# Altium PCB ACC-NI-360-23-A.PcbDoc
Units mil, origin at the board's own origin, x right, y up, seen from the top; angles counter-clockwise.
Board outline 2000 x 2500 mil, 2 copper layers (Top Layer, Bottom Layer), stack 22.756 mil thick; 31 components, 12 nets, 67 pads, 613 vias.
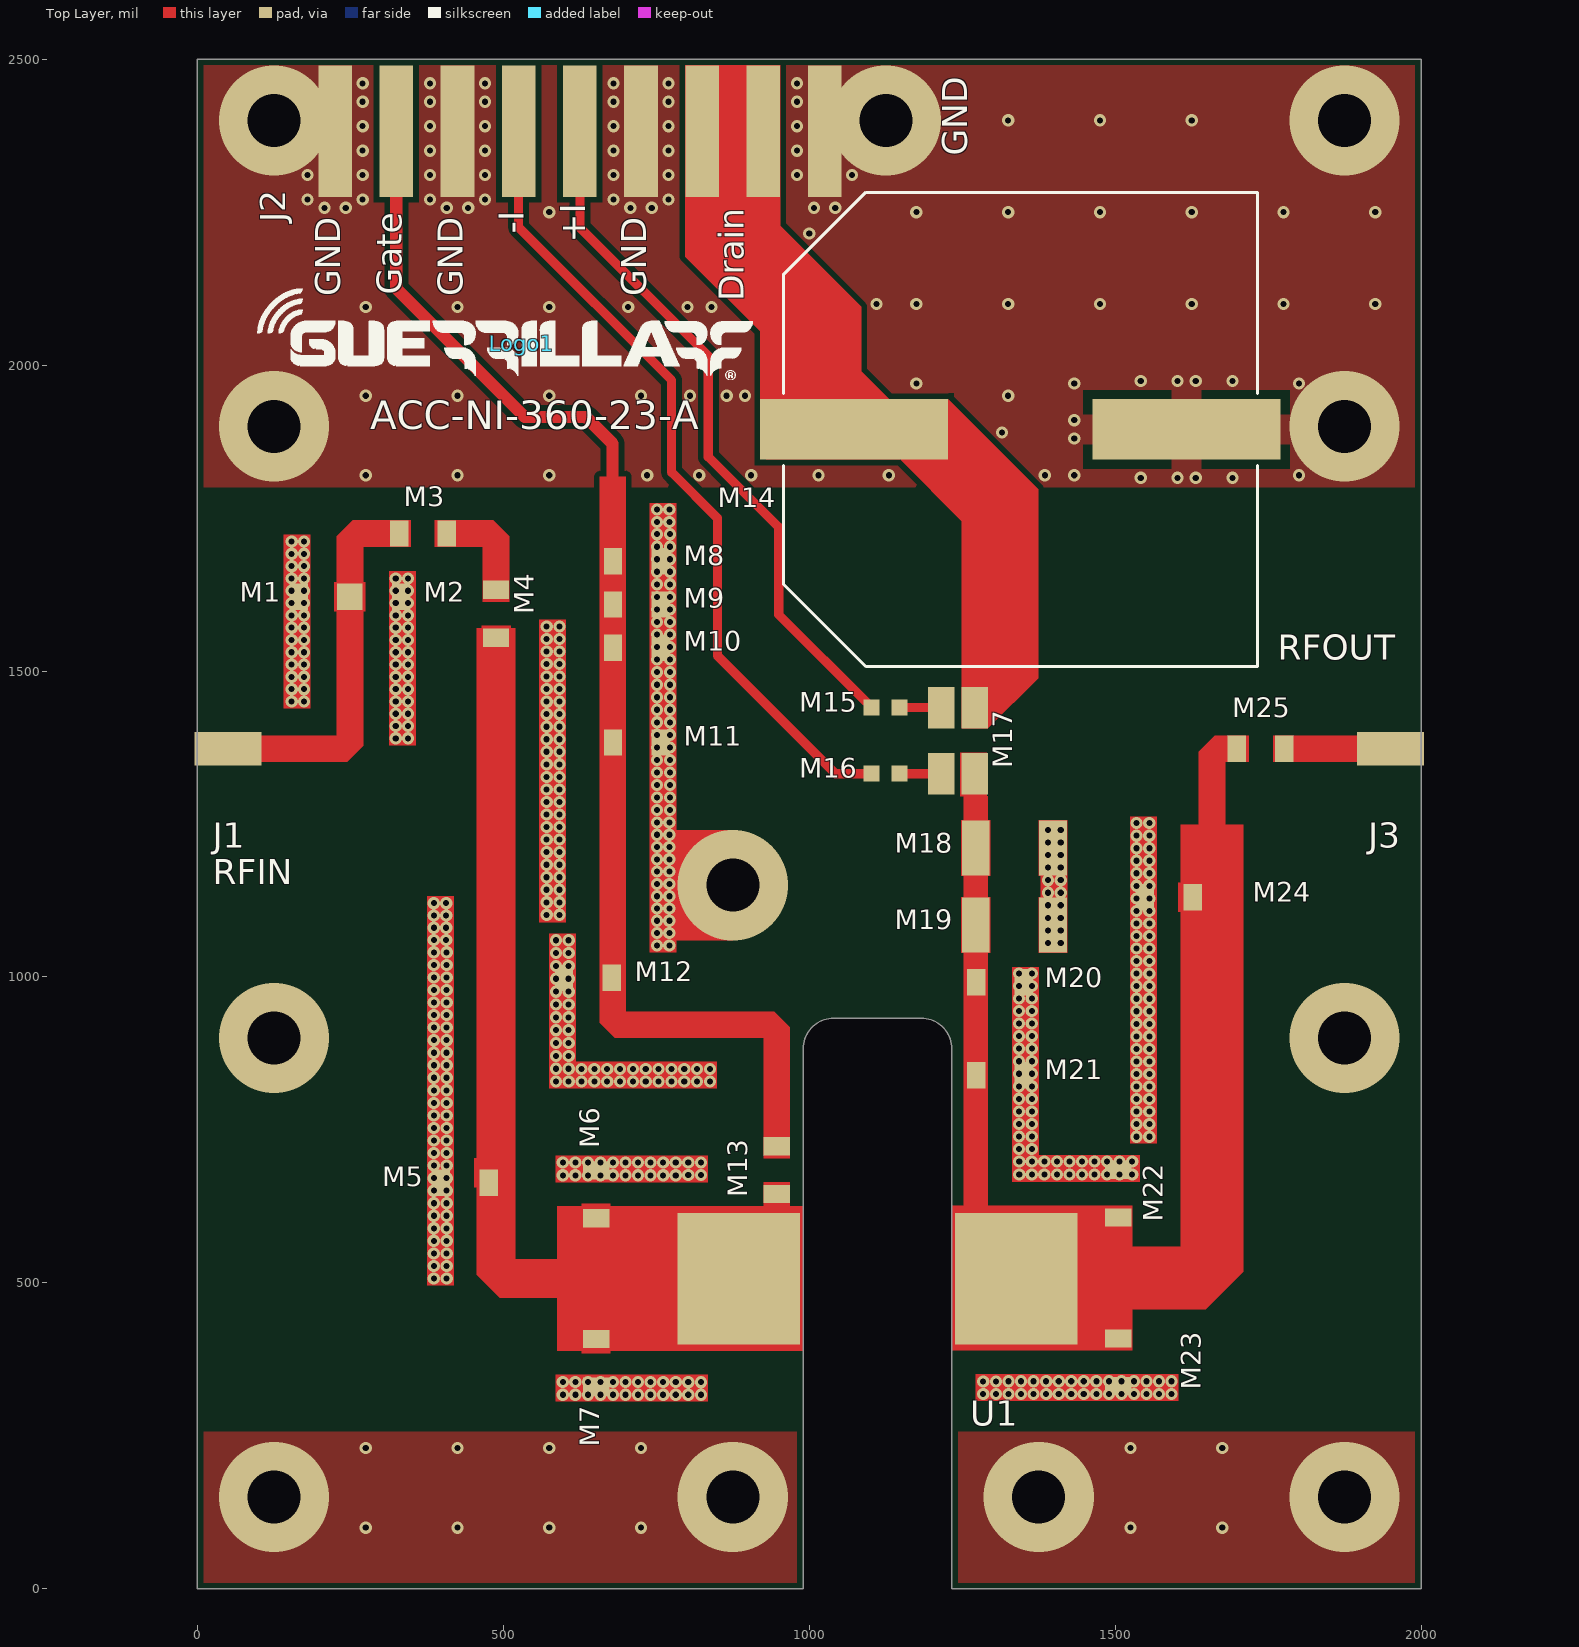
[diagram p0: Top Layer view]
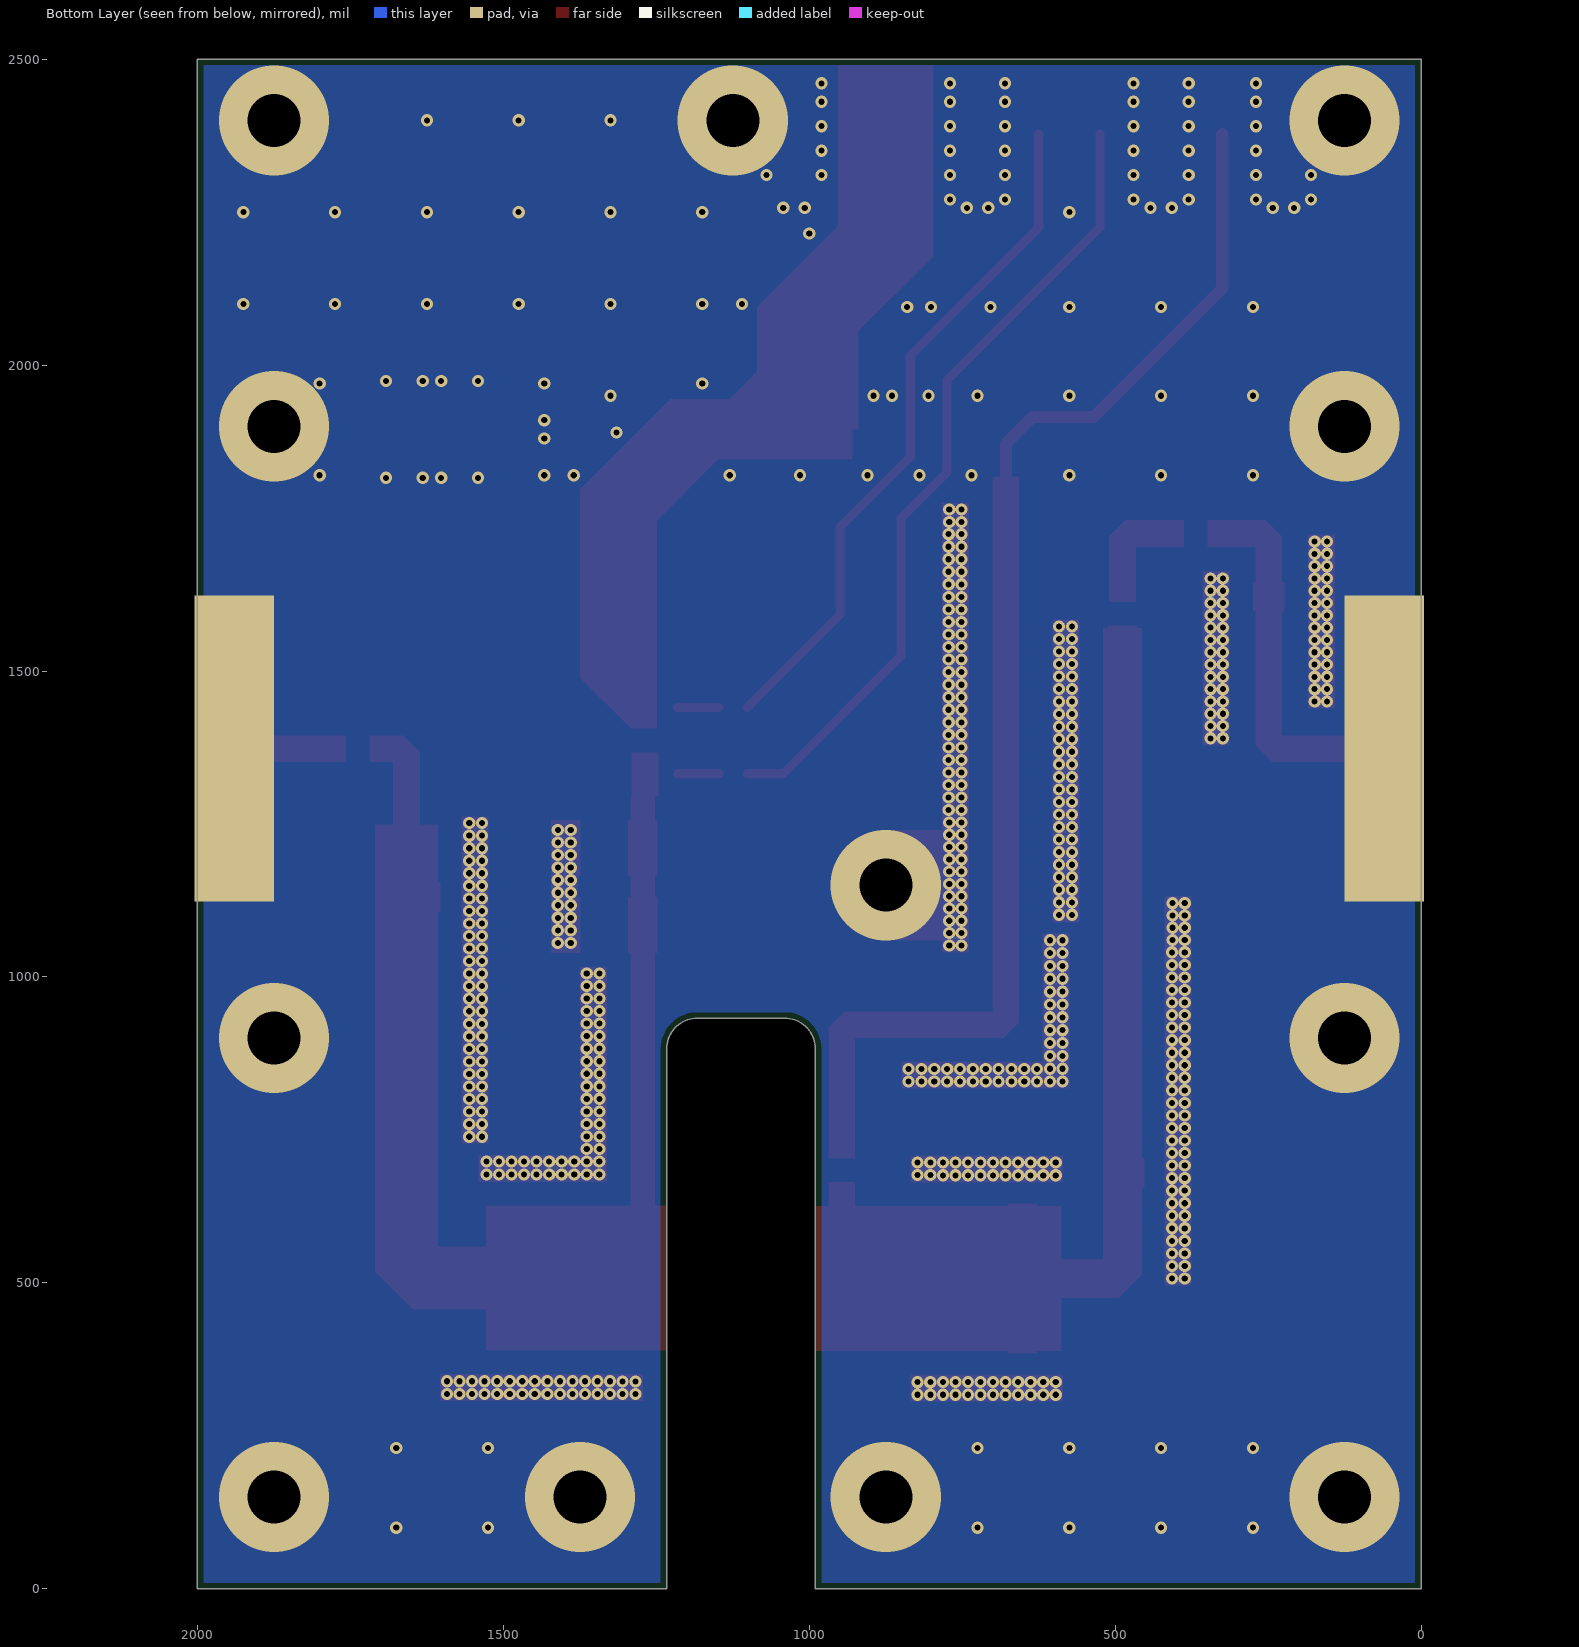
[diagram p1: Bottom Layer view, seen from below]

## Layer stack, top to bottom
Top Layer: signal copper 1.378
Dielectric 1: prepreg 20, RO4350B, Dk 3.48
Bottom Layer: signal copper 1.378

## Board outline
0,0 0,2500 2000,2500 2000,0 1233,0 1233,882.5 ccw(c1183,882.5) 1183,932.5 1040,932.5 ccw(c1040,882.5) 990,882.5 990,0

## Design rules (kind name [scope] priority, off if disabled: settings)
BackDrilling [IsVia and not InNet('GND')] p1: maxstublength=5 usetopbackdrill=TRUE usebottombackdrill=TRUE holeoversize=10 holetolplus=0.2 holetolminus=0.2
BoardOutlineClearance BoardOutlineClearance_Solder_Mask [OnLayer('Top Solder') Or OnLayer('Bottom Solder')] p1: gap=0 ignorepadtopadclearanceinfootprint=FALSE
BoardOutlineClearance [All] p2: gap=10 ignorepadtopadclearanceinfootprint=FALSE
Clearance Clearance_I/O [InNetClass('I/O') vs InNet('GND')] p1: gap=7 ignorepadtopadclearanceinfootprint=TRUE
Clearance Clearance_RF_Strip [InNetClass('RF_Strip') vs InNet('GND')] p2: gap=40 ignorepadtopadclearanceinfootprint=TRUE
Clearance Clearance_RF_15-15-8 [InNetClass('RF_15-15-8') vs InNet('GND')] p3: gap=15 ignorepadtopadclearanceinfootprint=TRUE
Clearance Clearance_RF_20-10-12 [InNetClass('RF_20-10-12') vs InNet('GND')] p4: gap=10 ignorepadtopadclearanceinfootprint=TRUE
Clearance Clearance_RF_30-20-16 [InNetClass('RF_30-20-16') vs InNet('GND')] p5: gap=20 ignorepadtopadclearanceinfootprint=TRUE
Clearance Clearance_RF_28-21-16_FR4 [InNetClass('RF_28-21-16_FR4') vs InNet('GND')] p6: gap=21 ignorepadtopadclearanceinfootprint=TRUE
Clearance Clearance_RF_15-27p5-8 [InNetClass('RF_15-27p5-8') vs InNet('GND')] p7: gap=27.5 ignorepadtopadclearanceinfootprint=TRUE
Clearance Clearance_RF_25-22-40_75ohm [InNetClass('RF_25-22-40_75ohm') vs InNet('GND')] p8: gap=22 ignorepadtopadclearanceinfootprint=TRUE
Clearance Clearance_GND [InNet('GND')] p9: gap=10 ignorepadtopadclearanceinfootprint=TRUE
Clearance [All] p10: gap=6 ignorepadtopadclearanceinfootprint=TRUE
ComponentClearance ComponentClearance_Heatsink [InComponent('All') And OnLayer('Top Layer') vs HasFootprint('Heatsink_wFid')] p1: gap=0 collisioncheckmode=3 verticalgap=0 showdistances=FALSE
ComponentClearance ComponentClearance_PCB_Frame [InComponent('All') And OnLayer('Top Layer') vs HasFootprint('PCB_Frame')] p2: gap=0 collisioncheckmode=3 verticalgap=0 showdistances=FALSE
ComponentClearance [All] p3: gap=10 collisioncheckmode=3 verticalgap=10 showdistances=TRUE
HoleSize [All] p1: absolutevalues=TRUE maxlimit=200 minlimit=8 maxpercent=80.000 minpercent=20.000
MinimumSolderMaskSliver [All] p1: minsoldermaskwidth=5
PlaneClearance [Not InNet('GND')] p1: clearance=20
PlaneConnect [InNet('GND')] p1: planeconnectstyle=Direct reliefexpansion=20 reliefentries=4 reliefconductorwidth=10 reliefairgap=10
PolygonConnect [All vs InNet('GND')] p1: connectstyle=Direct reliefconductorwidth=10 reliefentries=4 polygonreliefangle="90 Angle" airgapwidth=10
RoutingVias [All] p1: holewidth=10 width=20 viastyle="Through Hole" minholewidth=8 minwidth=18 maxholewidth=23.62 maxwidth=33.62
SilkToSilkClearance [All] p1: silktosilkclearance=5
SilkToSolderMaskClearance [IsPad] p1: minsilkscreentomaskgap=5 clearancetoexposedcopper=TRUE
SolderMaskExpansion [All] p1: expansion=1 istentingtop=FALSE
UnRoutedNet [All] p1: checkbadconnections=TRUE
Width [All] p1: maxlimit=100 minlimit=6 preferedwidth=10
22 further rules are at their usual default settings.

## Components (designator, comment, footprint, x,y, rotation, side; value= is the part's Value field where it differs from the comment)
F66 "Comment" PCB_Fab_30T-20G-16D_4003 166.62,-1553 r0 top locked
J1 "SMA Panel Mount_RevB" "SMA Panel Mount_RevB" 0,1373.14 r0 top locked
J2 "Header_H_9-Pin_100mil" Header_H_9-Pin_100mil 625,2500 r0 top
J3 "SMA Panel Mount_RevB" "SMA Panel Mount_RevB" 2000,1373.14 r180 top locked
Logo1 "GRF_2021_Full" GRF_2021_Full 530,2035 r0 top
M1 "0805_30x70x42" 0805_30x70x42 204.41,1621.17 r0 top
M2 "0805_30x70x42" 0805_30x70x42 293.78,1621.17 r180 top
M3 "0805_30x70x42" 0805_30x70x42 368.59,1724.91 r180 top
M4 "0805_30x70x42" 0805_30x70x42 488.07,1593.61 r90 top
M5 "0805_30x70x42" 0805_30x70x42 436.89,663.5 r0 top
M6 "0805_30x70x42" 0805_30x70x42 651.85,644.8 r270 top (schematic designator M7)
M7 "0805_30x70x42" 0805_30x70x42 651.85,369.21 r90 top (schematic designator M6)
M8 "0805_30x70x42" 0805_30x70x42 718.31,1679.56 r180 top
M9 "0805_30x70x42" 0805_30x70x42 718.31,1608.69 r180 top
M10 "0805_30x70x42" 0805_30x70x42 718.31,1537.82 r180 top
M11 "0805_30x70x42" 0805_30x70x42 718.31,1383.3 r180 top
M12 "0805_30x70x42" 0805_30x70x42 638.19,998.89 r0 top
M13 "0805_30x70x42" 0805_30x70x42 946.74,684.17 r90 top
M14 "Comment" Panasonic_K-Size 1345,1895 r0 top
M15 "0402_26x26x20" 0402_26x26x20 1124.41,1440.25 r180 top
M16 "0402_26x26x20" 0402_26x26x20 1124.41,1332.25 r180 top
M17 "Ohmite_LVK12" Ohmite_LVK12 1243.01,1386.25 r270 top
M18 "1210_45x120x75" 1210_45x120x75 1335.32,1211.08 r0 top
M19 "1210_45x120x75" 1210_45x120x75 1335.32,1084.76 r0 top
M20 "0805_30x70x42" 0805_30x70x42 1311.7,991.25 r180 top
M21 "0805_30x70x42" 0805_30x70x42 1311.7,839.22 r180 top
M22 "0805_30x70x42" 0805_30x70x42 1505,645.78 r270 top
M23 "0805_30x70x42" 0805_30x70x42 1505,370.19 r90 top
M24 "0805_30x70x42" 0805_30x70x42 1587.57,1130.03 r0 top
M25 "0805_30x70x42" 0805_30x70x42 1737.48,1373.14 r180 top
U1 "ACC-NI-360_RevA" ACC-NI-360_RevA 1111.5,507 r0 top locked

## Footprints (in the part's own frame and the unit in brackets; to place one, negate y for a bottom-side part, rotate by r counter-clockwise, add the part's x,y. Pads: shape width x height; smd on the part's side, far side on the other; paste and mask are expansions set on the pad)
0402_26x26x20 [mil] "0402 RL (RF Choke)"
  rect 26x26 smd: 1(-23,0) 2(23,0)
0805_30x70x42 [mil] "Generic 0805 SMD"
  rect 30x43 smd: 1(-39,0) 2(39,0)
1210_45x120x75 [mil] "Generic 1210 SMD"
  rect 45x90 smd: 1(-63,0) 2(63,0)
ACC-NI-360_RevA [mil] "Standard Footprint"
  rect 200.5x215 smd paste-3937.01: 1(226.75,0) 2(-226.75,0)
GRF_2021_Full [mil] "2021 Guerrilla RF Logo"
  silkscreen extent -432,-59 378,90
Header_H_9-Pin_100mil [mil] "Generic Flat Header"
  rect 55x215 smd paste-28: 1(-400,-117.5) 2(-300,-117.5) 3(-200,-117.5) 4(-100,-117.5) 5(0,-117.5) 6(100,-117.5) 7(200,-117.5) 8(300,-117.5) 9(400,-117.5)
Ohmite_LVK12 [mil] "Current Sense Resistor"
  rect 68x43 smd: 1(-54,-27.5) 2(54,-27.5) 3(54,27.5) 4(-54,27.5)
Panasonic_K-Size [mil] "EEV-FK2A221M Capacitor"
  rect 307x98.5 smd: 1(271.65,0) 2(-271.65,0)
  silkscreen extent -387,-387 387,387
PCB_Fab_30T-20G-16D_4003 [mil] "STD RF&Stack  30mil RF 20mil Gap  16mil Dielectric"
"SMA Panel Mount_RevB" [mil] "901-2GB100000AE"
  rect 110x55 smd paste-50: 1(50,0)
  rect 130x500 smd far side paste-50: 2(60,0)

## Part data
J1 J3: library part RF_Conn
J2: library part Header_9-Pin, "Header 9-Pin"
Logo1: library part GRF_Logo, "=CurrentFootprint"
M1 M2 M3 M4 M5 M6 M7 M8 M9 M10 M11 M12 M14 M18 M19 M20 M21 M22 M23 M24 M25: library part Capacitor
M13 M15 M16: library part Resistor
M17: library part Resistor_Ohmite_Current_Sense
U1: library part ACC-NI-360, "ACC-NI-360"

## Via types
v1: diameter 20/20 (per signal layer), hole 10, Top Layer to Bottom Layer, tented top, 486 vias
v2: diameter 20/20 (per signal layer), hole 10, Top Layer to Bottom Layer, 115 vias
v3: diameter 180/180 (per signal layer), hole 86.61, Top Layer to Bottom Layer, 12 vias

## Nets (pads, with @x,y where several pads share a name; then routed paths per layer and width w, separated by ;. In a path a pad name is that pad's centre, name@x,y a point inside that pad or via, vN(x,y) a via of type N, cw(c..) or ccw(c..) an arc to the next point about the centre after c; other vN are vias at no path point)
GND: J1.2 J2.1 J2.3 J2.6 J2.9 J3.2 M1.1 M2.1 M5.1 M6.1 M7.1 M8.1 M9.1 M10.1 M11.1 M12.1 M14.1 M18.2 M19.2 M20.1 M21.1 M22.1 M23.1 M24.1
  other v1: 597.16,317.21 617.66,317.21 638.16,317.21 658.66,317.21 679.16,317.21 699.66,317.21 720.16,317.21 740.66,317.21 761.16,317.21 781.66,317.21 802.16,317.21 823.16,317.21 1284.14,318.19 1305.14,318.19 1325.64,318.19 1346.14,318.19 1366.64,318.19 1387.14,318.19 1407.64,318.19 1428.14,318.19 1448.64,318.19 1469.14,318.19 1489.64,318.19 1510.14,318.19 1530.64,318.19 1551.14,318.19 1571.64,318.19 1592.14,318.19 597.16,338.21 617.66,338.21 638.16,338.21 658.66,338.21 679.16,338.21 699.66,338.21 720.16,338.21 740.66,338.21 761.16,338.21 781.66,338.21 802.16,337.71 823.16,337.71 1284.14,338.69 1305.14,338.69 1325.64,339.19 1346.14,339.19 1366.64,339.19 1387.14,339.19 1407.64,339.19 1428.14,339.19 1448.64,339.19 1469.14,339.19 1489.64,339.19 1510.14,339.19 1530.64,339.19 1551.14,339.19 1571.64,339.19 1592.14,339.19 386.37,507.2 407.37,507.2 386.37,527.7 407.37,527.7 386.37,548.2 407.37,548.2 386.37,568.7 407.37,568.7 386.37,589.2 407.37,589.2 386.37,609.7 407.37,609.7 386.37,630.2 407.37,630.2 386.37,650.7 407.37,650.7 386.37,671.2 407.37,671.2 597.16,675.79 617.66,675.79 638.16,675.79 658.66,675.79 679.16,675.79 699.66,675.79 720.16,675.79 740.66,675.79 761.16,675.79 781.66,675.79 802.16,676.29 823.16,676.29 1343.19,677.28 1363.69,677.28 1384.19,677.28 1404.69,677.28 1425.19,677.28 1445.69,677.28 1466.19,677.28 1486.69,677.28 1507.19,677.28 1527.69,677.28 386.37,691.7 407.37,691.7 597.16,696.79 617.66,696.79 638.16,696.79 658.66,696.79 679.16,696.79 699.66,696.79 720.16,696.79 740.66,696.79 761.16,696.79 781.66,696.79 802.16,696.79 823.16,696.79 1343.19,698.28 1363.69,698.28 1384.19,698.28 1404.69,698.28 1425.19,698.28 1445.69,698.28 1466.19,698.28 1486.69,698.28 1507.19,698.28 1527.69,698.28 386.37,712.2 407.37,712.2 1342.69,718.78 1363.69,718.78 386.37,732.7 407.37,732.7 1342.69,739.28 1363.69,739.28 1534.79,738.93 1555.79,738.93 386.37,753.2 407.37,753.2 1534.79,759.43 1555.79,759.43 1342.69,759.78 1363.69,759.78 386.37,773.7 407.37,773.7 1342.69,780.28 1363.69,780.28 1534.79,779.93 1555.79,779.93 386.37,794.2 407.37,794.2 1534.79,800.43 1555.79,800.43 1342.69,800.78 1363.69,800.78 386.37,814.7 407.37,814.7 1342.69,821.28 1363.69,821.28 1534.79,820.93 1555.79,820.93 586.19,829.02 606.69,829.02 627.69,829.02 648.69,829.02 669.69,829.02 690.69,829.02 711.69,829.02 732.69,829.02 753.69,829.02 774.69,829.02 795.69,829.02 816.69,829.02 837.69,829.02 386.37,835.2 407.37,835.2 1534.79,841.43 1555.79,841.43 1342.69,841.78 1363.69,841.78 586.19,850.02 606.69,850.02 627.69,849.52 648.69,849.52 669.69,849.52 690.69,849.52 711.69,849.52 732.69,849.52 753.69,849.52 774.69,849.52 795.69,849.52 816.69,849.52 837.69,849.52 386.37,855.7 407.37,855.7 1342.69,862.28 1363.69,862.28 1534.79,861.93 1555.79,861.93 586.19,871.02 606.69,871.02 386.37,876.2 407.37,876.2 1534.79,882.43 1555.79,882.43 1342.69,882.78 1363.69,882.78 586.19,892.02 606.69,892.02 386.37,896.7 407.37,896.7 1342.69,903.28 1363.69,903.28 1534.79,902.93 1555.79,902.93 586.19,913.02 606.69,913.02 386.37,917.2 407.37,917.2 1534.79,923.43 1555.79,923.43 1342.69,923.78 1363.69,923.78 586.19,934.02 606.69,934.02 386.37,937.7 407.37,937.7 1342.69,944.28 1363.69,944.28 1534.79,943.93 1555.79,943.93 586.19,955.02 606.69,955.02 386.37,958.2 407.37,958.2 1534.79,964.43 1555.79,964.43 1342.69,964.78 1363.69,964.78 586.19,976.02 606.69,976.02 386.37,978.7 407.37,978.7 1342.69,985.28 1363.69,985.28 1534.79,984.93 1555.79,984.93 586.19,997.02 606.69,997.02 386.37,999.2 407.37,999.2 1534.79,1005.43 1555.79,1005.43 1342.69,1005.78 1363.69,1005.78 586.19,1018.02 606.69,1018.02 386.37,1019.7 407.37,1019.7 1534.79,1025.93 1555.79,1025.93 586.19,1039.02 606.69,1039.02 386.37,1040.2 407.37,1040.2 1534.79,1046.43 1555.79,1046.43 751.18,1051.58 771.28,1051.58 1389.94,1055.67 1410.94,1055.67 386.37,1060.3 406.47,1060.3 586.19,1060.02 606.69,1060.02 1534.79,1066.93 1555.79,1066.93 751.18,1071.68 771.28,1071.68 1389.94,1076.17 1410.94,1076.17 386.37,1080.4 406.47,1080.4 1534.79,1087.43 1555.79,1087.43 751.18,1091.78 771.28,1091.78 1389.94,1096.67 1410.94,1096.67 386.37,1100.5 406.47,1100.5 570.75,1101.49 591.75,1101.49 1534.79,1107.93 1555.79,1107.93 751.18,1111.88 771.28,1111.88 1389.94,1117.17 1410.94,1117.17 386.37,1120.6 406.47,1120.6 570.75,1121.99 591.75,1121.99 1534.79,1128.43 1555.79,1128.43 751.18,1131.98 771.28,1131.98 1389.94,1137.67 1410.94,1137.67 570.75,1142.49 591.75,1142.49 1534.79,1148.93 1555.79,1148.93 751.18,1152.08 771.28,1152.08 1389.94,1158.17 1410.94,1158.17 570.75,1162.99 591.75,1162.99 1534.79,1169.43 1555.79,1169.43 751.18,1172.18 771.28,1172.18 1389.94,1178.67 1410.94,1178.67 570.75,1183.49 591.75,1183.49 1534.79,1189.93 1555.79,1189.93 751.18,1192.28 771.28,1192.28 1389.94,1199.17 1410.94,1199.17 570.75,1203.99 591.75,1203.99 1534.79,1210.43 1555.79,1210.43 751.18,1212.38 771.28,1212.38 1389.94,1219.67 1410.94,1219.67 570.75,1224.49 591.75,1224.49 1534.79,1230.93 1555.79,1230.93 751.18,1232.48 771.28,1232.48 1389.94,1240.17 1410.94,1240.17 570.75,1244.99 591.75,1244.99 1534.79,1251.43 1555.79,1251.43 751.18,1252.58 771.28,1252.58 570.75,1265.49 591.75,1265.49 751.18,1272.68 772.18,1272.68 570.75,1285.99 591.75,1285.99 751.18,1293.18 772.18,1293.18 570.75,1306.49 591.75,1306.49 751.18,1313.68 772.18,1313.68 570.75,1326.99 591.75,1326.99 751.18,1334.18 772.18,1334.18 570.75,1347.49 591.75,1347.49 751.18,1354.68 772.18,1354.68 570.75,1367.99 591.75,1367.99 751.18,1375.18 772.18,1375.18 570.75,1388.49 591.75,1388.49 324.12,1390.02 344.22,1390.02 751.18,1395.68 772.18,1395.68 570.75,1408.99 591.75,1408.99 324.12,1410.12 344.22,1410.12 751.18,1416.18 772.18,1416.18 570.75,1429.49 591.75,1429.49 324.12,1430.22 344.22,1430.22 751.18,1436.68 772.18,1436.68 153.97,1450.32 174.07,1450.32 324.12,1450.32 344.22,1450.32 570.75,1449.99 591.75,1449.99 751.18,1457.18 772.18,1457.18 153.97,1470.42 174.07,1470.42 324.12,1470.42 344.22,1470.42 570.75,1470.49 591.75,1470.49 751.18,1477.68 772.18,1477.68 153.97,1490.52 174.07,1490.52 324.12,1490.52 344.22,1490.52 570.75,1490.99 591.75,1490.99 751.18,1498.18 772.18,1498.18 153.97,1510.62 174.07,1510.62 324.12,1510.62 344.22,1510.62 570.75,1511.49 591.75,1511.49 751.18,1518.68 772.18,1518.68 153.97,1530.72 174.07,1530.72 324.12,1530.72 344.22,1530.72 570.75,1531.99 591.75,1531.99 751.18,1539.18 772.18,1539.18 153.97,1550.82 174.07,1550.82 324.12,1550.82 344.22,1550.82 570.75,1552.49 591.75,1552.49 751.18,1559.68 772.18,1559.68 153.97,1570.92 174.07,1570.92 324.12,1570.92 344.22,1570.92 570.75,1572.99 591.75,1572.99 751.18,1580.18 772.18,1580.18 153.97,1591.02 174.07,1591.02 324.12,1591.02 344.22,1591.02 751.18,1600.68 772.18,1600.68 153.97,1611.12 174.07,1611.12 324.12,1611.12 344.22,1611.12 751.18,1621.18 772.18,1621.18 153.97,1631.22 174.07,1631.22 324.12,1631.22 344.22,1631.22 751.18,1641.68 772.18,1641.68 153.97,1651.32 174.07,1651.32 324.12,1651.32 344.22,1651.32 751.18,1662.18 772.18,1662.18 153.97,1671.42 174.07,1671.42 751.18,1682.68 772.18,1682.68 153.97,1691.52 174.07,1691.52 751.18,1703.18 772.18,1703.18 153.97,1711.62 174.07,1711.62 751.18,1723.68 772.18,1723.68 751.18,1743.78 771.28,1743.78 751.18,1763.88 771.28,1763.88
  other v2: 275,100 425,100 575,100 725,100 1525,100 1675,100 275,230 425,230 575,230 725,230 1525,230 1675,230 1541.65,1815.79 1601.65,1815.79 1631.65,1815.79 1691.65,1815.79 275,1820 425,1820 575,1820 735,1820 820,1820 905,1820 1015,1820 1130,1820 1385,1820 1433.11,1820 1800.2,1820 1433.11,1880 1315,1890 1433.11,1910 275,1950 425,1950 575,1950 725,1950 805,1950 865,1950 895,1950 1325,1950 1175,1970 1433.11,1970 1800.2,1970 1541.65,1974.21 1601.65,1974.21 1631.65,1974.21 1691.65,1974.21 275,2095 425,2095 575,2095 704,2095 801,2095 840,2095 1110,2100 1175,2100 1325,2100 1475,2100 1625,2100 1775,2100 1925,2100 1000,2215 575,2250 1175,2250 1325,2250 1475,2250 1625,2250 1775,2250 1925,2250 207.5,2257 242.5,2257 407.5,2257 442.5,2257 707.5,2257 742.5,2257 1007.5,2257 1042.5,2257 180,2270.5 270,2270.5 380,2270.5 470,2270.5 680,2270.5 770,2270.5 180,2310.5 270,2310.5 380,2310.5 470,2310.5 680,2310.5 770,2310.5 980,2310.5 1070,2310.5 270,2350.5 380,2350.5 470,2350.5 680,2350.5 770,2350.5 980,2350.5 270,2390.5 380,2390.5 470,2390.5 680,2390.5 770,2390.5 980,2390.5 1325,2400 1475,2400 1625,2400 270,2430.5 380,2430.5 470,2430.5 680,2430.5 770,2430.5 980,2430.5 270,2460.5 380,2460.5 470,2460.5 680,2460.5 770,2460.5 980,2460.5
  other v3: 125,150 875,150 1375,150 1875,150 125,900 1875,900 875,1150 125,1900 1875,1900 125,2400 1125,2400 1875,2400
NetJ1_1: J1.1 M1.2 M2.2 M3.2
NetJ2_2: J2.2 M8.2 M9.2 M10.2 M11.2 M12.2 M13.2 | length 765.1
  Top Layer w20: J2.2@325,2377.5 325,2125 535,1915 635,1915 678.35,1871.65 678.35,1817.35
NetJ2_4: J2.4 M16.2 | length 1318.4
  Top Layer w15: J2.4@525,2377.5 525,2225 775,1975 775,1825 850,1750 850,1525 1042.75,1332.25 M16.2
NetJ2_5: J2.5 M15.2 | length 1135.2
  Top Layer w15: J2.5@625,2377.5 625,2225 835,2015 835,1850 950,1735 950,1592.25 1095.91,1446.34 1095.91,1445.75 M15.2 M15.2@1102,1440.25
NetJ2_7: J2.7 J2.8 M14.2 M17.4
NetJ3_1: J3.1 M25.1
NetM3_1: M3.1 M4.2
NetM4_1: M4.1 M5.2 M6.2 M7.2 M13.1 U1.2
NetM15_1: M15.1 M17.1 | length 68.1
  Top Layer w15: M15.1 M17.1
NetM16_1: M16.1 M17.2 | length 68.1
  Top Layer w15: M16.1 M17.2
NetM17_3: M17.3 M18.1 M19.1 M20.2 M21.2 M22.2 M23.2 M24.2 M25.2 U1.1

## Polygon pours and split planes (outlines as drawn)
GND on Top Layer "NONET_L-01_P-001" (solid, pour order 18): 0,2500 0,1800 2000,1800 2000,2500
GND on Top Layer "NONET_L-01_P-001" (solid, pour order 16): 0,0 0,257 2000,257 2000,0
GND on Bottom Layer "NONET_L-01_P-001" (solid, pour order 17): 0,2500 0,0 2000,0 2000,2500
no net on Top Solder "NONET_L-01_P-001" (solid): 0,1775 2000,1775 2000,282 0,282

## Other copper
Top Layer:
  region net GND: 875,1240 770.69,1240 770.69,1060 875,1060
  region net GND: 575.2,818.02 849,818.02 849,861.33 618.5,861.33 618.5,1071 575.2,1071
  region net GND: 184.73,1439 141.42,1439 141.42,1723 184.73,1723
  region net NetJ2_7: 1292.01,1406.25 1249.01,1406.25 1249.01,1745.2 1148.46,1845.75 929.85,1845.75 929.85,1944.25 1226.85,1944.25 1374.01,1797.09 1374.01,1488.25
  region net NetJ2_7: 797.5,2490 797.5,2177.5 919.85,2055.15 919.85,1895 1226.85,1895 1226.85,1944.25 1130.75,1944.25 1084.85,1990.15 1084.85,2095.15 952.5,2227.5 952.5,2490
  region net GND: 739.37,1774 739.37,1040 782.68,1040 782.68,1774
  region net NetJ2_2: 925.67,703.85 967.8,703.85 967.8,917.55 942.52,942.83 700,942.83 700,1762.23 700,1817.35 657.87,1817.35 657.87,1762.23 657.87,925.28 682.45,900.7 925.67,900.7
  region net GND: 586,707.79 586,664.48 834,664.48 834,707.79
  region net NetM4_1: 588.47,625.11 627.84,625.11 627.84,629.05 675.08,629.05 675.08,625.11 925.67,625.11 925.67,664.48 967.8,664.48 967.8,625.11 990.04,625.11 990.04,388.89 675.08,388.89 675.08,384.95 627.84,384.95 627.84,388.89 588.47,388.89
  region net GND: 558.94,1089.68 602.25,1089.68 602.25,1584 558.94,1584
  region net NetM4_1: 452.64,656.61 456.58,656.61 456.58,513.3 494.37,475.5 600,475.5 600,538.5 519.57,538.5 519.57,1569.99 511.7,1569.99 511.7,1573.93 464.45,1573.93 464.45,1569.99 456.58,1569.99 456.58,703.85 452.64,703.85
  region net NetJ1_1: 0,1394.64 227.6,1394.64 227.6,1597.55 223.66,1597.55 223.66,1644.8 227.6,1644.8 227.6,1720.26 253.75,1746.41 348.9,1746.41 348.9,1703.41 270.6,1703.41 270.6,1644.8 274.53,1644.8 274.53,1597.55 270.6,1597.55 270.6,1377.79 244.45,1351.64 0,1351.64
  region net GND: 313.47,1379 356.78,1379 356.78,1663.3 313.47,1663.3
  region net NetM3_1: 388.27,1703.41 466.57,1703.41 466.57,1613.3 509.57,1613.3 509.57,1720.26 483.42,1746.41 388.27,1746.41
  region net GND: 375.87,496 419.18,496 419.18,1132 375.87,1132
  region net GND: 586,306.21 586,349.52 834,349.52 834,306.21
  region net GND: 1272.33,307.2 1272.33,350.5 1603,350.5 1603,307.2
  region net GND: 1374.69,1039.48 1374.69,1130.03 1378.63,1130.03 1378.63,1165.8 1374.69,1165.8 1374.69,1256.35 1421.93,1256.35 1421.93,1039.48
  region net GND: 1331.38,665.46 1331.38,1016 1374.69,1016 1374.69,708.77 1540.04,708.77 1540.04,665.46
  region net NetM17_3: 1232.96,389.87 1232.96,626.09 1252.64,626.09 1252.64,1039.48 1248.7,1039.48 1248.7,1130.03 1252.64,1130.03 1252.64,1165.8 1248.7,1165.8 1248.7,1256.35 1252.64,1256.35 1252.64,1295.39 1246.74,1295.39 1246.74,1366.25 1290.04,1366.25 1290.04,1295.39 1292.01,1295.39 1292.01,1256.35 1295.95,1256.35 1295.95,1165.8 1292.01,1165.8 1292.01,1130.03 1295.95,1130.03 1295.95,1039.48 1292.01,1039.48 1292.01,626.09 1528.23,626.09 1528.23,559.17 1606.97,559.17 1606.97,1106.41 1603.03,1106.41 1603.03,1153.65 1606.97,1153.65 1606.97,1248.44 1636.65,1248.44 1636.65,1368.49 1662.8,1394.64 1718.59,1394.64 1718.59,1351.64 1679.65,1351.64 1679.65,1248.44 1709.33,1248.44 1709.33,518.22 1647.92,456.8 1528.23,456.8 1528.23,389.87
  region net NetJ3_1: 1757.96,1351.64 2000,1351.64 2000,1394.64 1757.96,1394.64
  region net GND: 1524.29,728 1524.29,1262 1567.6,1262 1567.6,728
  region net GND: 1374.69,1165.8 1421.93,1165.8 1421.93,1256.35 1374.69,1256.35
  region net GND: 1374.69,1165.8 1421.93,1165.8 1421.93,1256.35 1374.69,1256.35
  region net GND: 1374.69,1039.48 1421.93,1039.48 1421.93,1130.03 1374.69,1130.03

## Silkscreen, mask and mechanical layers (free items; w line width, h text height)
Top Overlay:
  text "GND" at 1272.42,2342.42 h70 r90
  text "-I" at 547.42,2214.28 h70 r90
  text "+I" at 647.42,2200.03 h70 r90
  text "Gate" at 347.42,2115.01 h70 r90
  text "GND" at 247.42,2112.42 h70 r90
  text "GND" at 447.42,2112.42 h70 r90
  text "GND" at 747.42,2112.42 h70 r90
  text "Drain" at 907.06,2104.45 h70 r90
  text "ACC-NI-360-23-A" at 282.58,1879.4 h80
  text "RFOUT" at 1765.44,1504.58 h70
  text "RFIN" at 25,1137.58 h70
Top Solder:
  drawing of 47 lines, arcs and shapes, not listed
Bottom Solder:
  region: 0,2500 2000,2500 2000,0 0,0
Board_Dimension:
  the board outline again, w10
Drill Drawing:
  lines w15: -769.1,-4328 4245.53,-4328 ; -769.1,-4028 4245.53,-4028 ; -218.22,-4478 -218.22,-3878 ; 371.62,-4478 371.62,-3878 ; 1461.3,-4478 1461.3,-3878 ; 1967.18,-4478 1967.18,-3878 ; 2700.98,-4478 2700.98,-3878 ; -769.1,-4478 4245.53,-4478 4245.53,-3878 -769.1,-3878 -769.1,-4478
  text "Symbol" at -679.1,-3983 h72
  text "Count" at -173.22,-3983 h72
  text "Hole Size" at 416.62,-3983 h72
  text "Plated" at 1506.3,-3983 h72
  text "Hole Type" at 2012.18,-3983 h72
  text "Drill Layer Pair" at 2745.98,-3983 h72
  text "601" at -173.22,-4133 h60
  text "10.00mil (0.254mm)" at 416.62,-4133 h60
  text "PTH" at 1506.3,-4133 h60
  text "Round" at 2012.18,-4133 h60
  text "Top Layer - Bottom Layer" at 2745.98,-4133 h60
  text "B" at -708.19,-4142.99 h66.67
  text "12" at -173.22,-4283 h60
  text "86.61mil (2.200mm)" at 416.62,-4283 h60
  text "PTH" at 1506.3,-4283 h60
  text "Round" at 2012.18,-4283 h60
  text "Top Layer - Bottom Layer" at 2745.98,-4283 h60
  text "M" at -708.19,-4292.99 h66.67
  text "613 Total" at -173.22,-4433 h60
Document:
  lines w10: -406.5,1671 -56.5,1371 ; -396.29,2052.94 258.87,1688.6 ; -31.5,1121 -56.5,1121 -56.5,1621 -31.5,1621 ; 250.92,1423.34 -399,2056 473.3,1725.14 ; 1379.77,2210 1514.39,2627.6 ; 1654.94,1321.84 2361.19,805.39 1824.88,1368.19 ; 2033,1118.11 2058,1118.11 2058,1618.11 2033,1618.11 ; 2058,1368.11 2408,1668.11 ; 1111.39,2010 1111.39,2210 1711.39,2210 1711.39,2010 1111.39,2010
  text "Note A" at -733.16,2081.8 h125

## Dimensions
0,0 to 0,2500 on Mechanical 16
0,0 to 2000,0 on Mechanical 16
